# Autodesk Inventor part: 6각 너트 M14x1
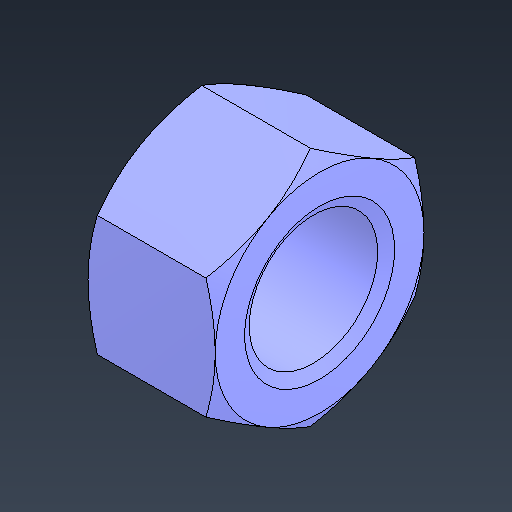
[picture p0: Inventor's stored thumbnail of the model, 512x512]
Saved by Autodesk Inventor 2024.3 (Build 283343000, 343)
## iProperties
Created: 2025-07
Part Number: 6각 너트 M14x1
Material: 강철, 연강
Description: 6각 너트 및 6각 가는 너트 - 스타일 1
Document SubType Name: Modeling
Designer: user
Density: 7.85 g/cm^3
Appearance: 기본값
Author: jhkim
Sending System: Autodesk Inventor 2026
Preprocessor: ST-DEVELOPER v20.1
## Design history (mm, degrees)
feature "Solid1"
node "솔리드1"
